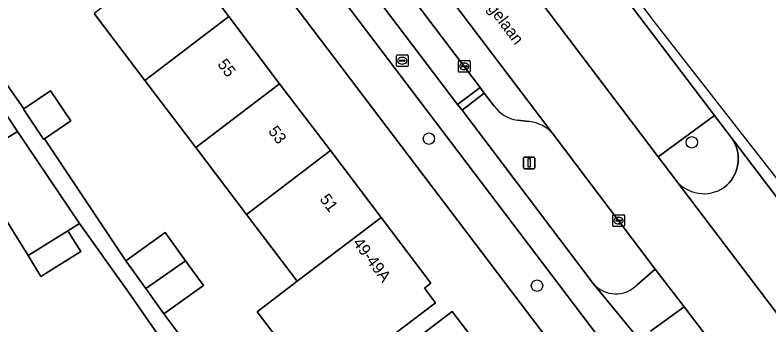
# Model space of a CAD drawing. Extents: x 159664 to 160323, y 385312 to 386115.
# Drawn here: x 160147.9 to 160212.4, y 385837.5 to 385864 of the extents above; entities that cross this region are included whole.
import ezdxf

# ---------------------------------------------------------------- set-up
doc = ezdxf.new("R2010")
doc.units = 0
for name, color, linetype in [('IMGEO_Berm_groen', 7, 'Continuous'), ('IMGEO_Boom', 7, 'Continuous'), ('IMGEO_Erf', 7, 'Continuous'), ('IMGEO_Fietspad_gesloten', 7, 'Continuous'), ('IMGEO_Kolk', 7, 'Continuous'), ('IMGEO_Lichtmast', 7, 'Continuous'), ('IMGEO_Openbare_ruimte_label', 7, 'Continuous'), ('IMGEO_Pand', 7, 'Continuous'), ('IMGEO_Pand_nummerreeks', 7, 'Continuous'), ('IMGEO_Parkeervlak_open', 7, 'Continuous'), ('IMGEO_Rijbaan_lokaal_gesloten', 7, 'Continuous'), ('IMGEO_Rioolput', 7, 'Continuous'), ('IMGEO_Verkeerseiland_groen', 7, 'Continuous'), ('IMGEO_Voetpad_open', 7, 'Continuous')]:
    doc.layers.add(name, color=color, linetype=linetype)

msp = doc.modelspace()

# ---------------------------------------------------------------- linework, layer by layer
at = {"layer": 'IMGEO_Berm_groen'}
for points in [[(160174.614, 385899.039), (160169.921, 385895.45), (160202.923, 385851.883), (160207.751, 385855.425)], [(160179.262, 385868.942), (160177.327, 385867.463), (160185.75, 385856.345), (160187.67, 385857.825)]]:
    msp.add_lwpolyline(points, close=True, dxfattribs=at)
for points in [[(160188.882, 385856.222), (160188.036, 385857.34), (160186.137, 385855.863), (160197.359, 385841.045)], [(160191.886, 385854.896), (160190.867, 385855.022)], [(160201.114, 385840.937), (160202.671, 385842.281), (160193.92, 385853.82)], [(160205.159, 385839.046), (160202.259, 385836.969)], [(160202.434, 385834.337), (160206.906, 385828.506), (160210.857, 385831.546), (160205.159, 385839.046)]]:
    msp.add_lwpolyline(points, dxfattribs=at)
for centre, radius, start, end in [((160191.266, 385857.924), 2.93, 215.52611, 262.16511), ((160191.589, 385851.873), 3.037, 39.86068, 84.38102), ((160199.286, 385842.7), 2.54, 220.65482, 316.05025)]:
    msp.add_arc(centre, radius, start, end, dxfattribs=at)
at = {"layer": 'IMGEO_Boom'}
for centre in [(160183.297, 385853.432), (160205.8, 385853.119), (160192.551, 385840.863)]:
    msp.add_circle(centre, 0.489, dxfattribs=at)
at = {"layer": 'IMGEO_Erf'}
for points in [[(160260.143, 385748.478), (160154.34, 385887.843), (160153.697, 385888.214), (160152.472, 385888.921), (160150.373, 385888.694), (160144.032, 385884.624)], [(160161.823, 385869.601), (160166.166, 385863.87), (160170.511, 385858.139), (160174.854, 385852.409), (160179.197, 385846.679), (160183.451, 385841.067), (160182.909, 385840.656), (160183.863, 385839.397), (160178.787, 385835.549), (160177.283, 385834.409), (160176.327, 385835.667), (160176.279, 385835.631), (160172.852, 385833.035), (160168.601, 385838.632), (160172.025, 385841.233), (160167.677, 385846.959), (160163.328, 385852.685), (160158.979, 385858.412), (160154.631, 385864.138)], [(160145.158, 385860.878), (160148.597, 385855.979), (160150.896, 385857.53), (160152.631, 385854.958), (160150.371, 385853.432), (160157.337, 385842.993), (160160.719, 385845.421), (160162.464, 385842.99), (160163.981, 385840.878), (160160.598, 385838.449), (160163.342, 385834.802)], [(160144.304, 385851.707), (160148.063, 385854.043), (160146.068, 385857.054)], [(160179.548, 385808.743), (160177.486, 385807.335), (160175.299, 385810.539), (160177.239, 385811.863), (160173.738, 385816.876), (160169.705, 385814.157), (160166.521, 385818.879), (160170.555, 385821.598), (160157.572, 385840.316), (160153.37, 385846.177), (160152.384, 385845.564), (160153.492, 385843.783), (160150.075, 385841.657), (160148.967, 385843.438), (160143.966, 385851.479)]]:
    msp.add_lwpolyline(points, dxfattribs=at)
msp.add_lwpolyline([(160208.692, 385793.17), (160204.334, 385798.89), (160199.977, 385804.609), (160195.619, 385810.328), (160191.261, 385816.048), (160186.904, 385821.767), (160182.547, 385827.485), (160178.162, 385833.241), (160181.313, 385835.637), (160185.293, 385838.663), (160189.676, 385832.899), (160194.027, 385827.176), (160198.379, 385821.452), (160202.731, 385815.729), (160207.083, 385810.005), (160211.435, 385804.281), (160215.786, 385798.558), (160220.204, 385792.748), (160215.947, 385789.652), (160213.003, 385787.512)], close=True, dxfattribs=at)
at = {"layer": 'IMGEO_Fietspad_gesloten'}
for points in [[(160201.804, 385835.617), (160197.359, 385841.045), (160186.137, 385855.863), (160185.75, 385856.345), (160177.327, 385867.463), (160175.871, 385869.409), (160168.561, 385878.986), (160168.182, 385879.472), (160161.323, 385888.557), (160159.511, 385890.971), (160157.24, 385893.946), (160149.098, 385905.226), (160147.316, 385907.817), (160144.932, 385911.316), (160142.935, 385909.961), (160147.03, 385903.951), (160154.766, 385893.221), (160263.854, 385749.476), (160272.35, 385738.304), (160298.51, 385703.942), (160300.884, 385700.823)], [(160202.671, 385842.281), (160201.114, 385840.937)], [(160202.259, 385836.969), (160205.159, 385839.046), (160202.671, 385842.281)], [(160197.359, 385841.045), (160201.804, 385835.617)]]:
    msp.add_lwpolyline(points, dxfattribs=at)
msp.add_arc((160199.286, 385842.7), 2.54, 220.65482, 316.05025, dxfattribs=at)
at = {"layer": 'IMGEO_Kolk'}
for p, q in [((160185.816, 385859.192), (160185.816, 385860.044)), ((160185.891, 385860.118), (160186.743, 385860.118)), ((160186.075, 385859.612), (160186.075, 385859.624)), ((160186.513, 385859.575), (160186.115, 385859.575)), ((160186.118, 385859.661), (160186.516, 385859.661)), ((160186.304, 385859.898), (160186.329, 385859.898)), ((160186.559, 385859.624), (160186.559, 385859.612)), ((160186.817, 385860.044), (160186.817, 385859.192)), ((160186.743, 385859.118), (160185.891, 385859.118)), ((160186.327, 385859.338), (160186.302, 385859.338)), ((160199.033, 385846.005), (160199.033, 385846.857)), ((160199.108, 385846.931), (160199.96, 385846.931)), ((160199.521, 385846.711), (160199.546, 385846.711)), ((160200.034, 385846.857), (160200.034, 385846.005)), ((160199.292, 385846.425), (160199.292, 385846.437)), ((160199.73, 385846.388), (160199.332, 385846.388)), ((160199.335, 385846.474), (160199.733, 385846.474)), ((160199.544, 385846.151), (160199.519, 385846.151)), ((160199.776, 385846.437), (160199.776, 385846.425)), ((160199.96, 385845.931), (160199.108, 385845.931))]:
    msp.add_line(p, q, dxfattribs=at)
for points in [[(160185.816, 385859.192), (160185.816, 385860.044)], [(160185.891, 385860.118), (160186.743, 385860.118)], [(160186.817, 385860.044), (160186.817, 385859.192)], [(160186.743, 385859.118), (160185.891, 385859.118)], [(160199.033, 385846.005), (160199.033, 385846.857)], [(160199.108, 385846.931), (160199.96, 385846.931)], [(160200.034, 385846.857), (160200.034, 385846.005)], [(160199.96, 385845.931), (160199.108, 385845.931)]]:
    msp.add_lwpolyline(points, dxfattribs=at)
for centre, radius, start, end in [((160185.893, 385860.042), 0.0765, 91.55205, 178.44795), ((160185.893, 385860.042), 0.0765, 91.55205, 178.44795), ((160186.115, 385859.621), 0.0403, 85.87752, 175.75265), ((160186.112, 385859.611), 0.0366, 178.93798, 274.71019), ((160186.516, 385859.618), 0.043, 264.86636, 352.45326), ((160186.52, 385859.623), 0.0386, 1.73085, 96.63898), ((160186.741, 385860.042), 0.0765, 1.55205, 88.44795), ((160186.741, 385860.042), 0.0765, 1.55205, 88.44795), ((160185.893, 385859.194), 0.0765, 181.55205, 268.44795), ((160185.893, 385859.194), 0.0765, 181.55205, 268.44795), ((160186.741, 385859.194), 0.0765, 271.55205, 358.44795), ((160186.741, 385859.194), 0.0765, 271.55205, 358.44795), ((160199.11, 385846.855), 0.0765, 91.55205, 178.44795), ((160199.11, 385846.855), 0.0765, 91.55205, 178.44795), ((160199.958, 385846.855), 0.0765, 1.55205, 88.44795), ((160199.958, 385846.855), 0.0765, 1.55205, 88.44795), ((160199.11, 385846.007), 0.0765, 181.55205, 268.44795), ((160199.11, 385846.007), 0.0765, 181.55205, 268.44795), ((160199.332, 385846.434), 0.0403, 85.87752, 175.75265), ((160199.329, 385846.424), 0.0366, 178.93798, 274.71019), ((160199.733, 385846.431), 0.043, 264.86636, 352.45326), ((160199.737, 385846.436), 0.0386, 1.73085, 96.63898), ((160199.958, 385846.007), 0.0765, 271.55205, 358.44795), ((160199.958, 385846.007), 0.0765, 271.55205, 358.44795)]:
    msp.add_arc(centre, radius, start, end, dxfattribs=at)
for centre, major_axis, ratio, start_param, end_param in [((160186.303, 385859.618), (-0.387, 0.002), 0.722429, 4.712389, 7.853982), ((160186.328, 385859.618), (-0.39, 0.002), 0.717154, 1.570796, 4.712389), ((160199.52, 385846.431), (-0.387, 0.002), 0.722429, 4.712389, 7.853982), ((160199.545, 385846.431), (-0.39, 0.002), 0.717154, 1.570796, 4.712389)]:
    msp.add_ellipse(centre, major_axis=major_axis, ratio=ratio, start_param=start_param, end_param=end_param, dxfattribs=at)
at = {"layer": 'IMGEO_Lichtmast'}
for p, q in [((160191.483, 385851.859), (160192.273, 385851.859)), ((160192.273, 385851.859), (160191.483, 385851.859)), ((160191.383, 385850.959), (160191.383, 385851.759)), ((160191.383, 385851.759), (160191.383, 385850.959)), ((160192.373, 385851.759), (160192.373, 385850.959)), ((160192.373, 385850.959), (160192.373, 385851.759)), ((160192.273, 385850.859), (160191.483, 385850.859)), ((160191.483, 385850.859), (160192.273, 385850.859))]:
    msp.add_line(p, q, dxfattribs=at)
msp.add_lwpolyline([(160191.803, 385851.734), (160191.953, 385851.734), (160191.953, 385850.984), (160191.803, 385850.984), (160191.803, 385851.734)], dxfattribs=at)
for centre, start, end in [((160191.483, 385851.759), 90, 180), ((160191.483, 385851.759), 90, 180), ((160192.273, 385851.759), 0, 90), ((160192.273, 385851.759), 360, 90), ((160191.483, 385850.959), 180, 270), ((160191.483, 385850.959), 180, 270), ((160192.273, 385850.959), 270, 0), ((160192.273, 385850.959), 270, 0)]:
    msp.add_arc(centre, 0.1, start, end, dxfattribs=at)
at = {"layer": 'IMGEO_Pand'}
for points in [[(160166.166, 385863.87), (160161.823, 385869.601), (160154.631, 385864.138), (160158.979, 385858.412)], [(160158.979, 385858.412), (160163.328, 385852.685), (160170.511, 385858.139), (160166.166, 385863.87)], [(160174.854, 385852.409), (160170.511, 385858.139), (160163.328, 385852.685), (160167.677, 385846.959)], [(160148.597, 385855.979), (160148.568, 385855.96), (160150.304, 385853.387), (160150.371, 385853.432), (160152.631, 385854.958), (160150.896, 385857.53)], [(160148.063, 385854.043), (160144.304, 385851.707), (160143.966, 385851.479), (160148.967, 385843.438), (160152.384, 385845.564), (160153.37, 385846.177)], [(160167.677, 385846.959), (160172.025, 385841.233), (160179.197, 385846.679), (160174.854, 385852.409)], [(160183.863, 385839.397), (160182.909, 385840.656), (160183.451, 385841.067), (160179.197, 385846.679), (160172.025, 385841.233), (160168.601, 385838.632), (160172.852, 385833.035), (160176.279, 385835.631), (160176.327, 385835.667), (160177.283, 385834.409), (160178.787, 385835.549)], [(160148.967, 385843.438), (160150.075, 385841.657), (160153.492, 385843.783), (160152.384, 385845.564)], [(160157.337, 385842.993), (160159.042, 385840.617), (160162.464, 385842.99), (160160.719, 385845.421)], [(160163.981, 385840.878), (160162.464, 385842.99), (160159.042, 385840.617), (160160.598, 385838.449)], [(160189.676, 385832.899), (160185.293, 385838.663), (160181.313, 385835.637), (160178.162, 385833.241), (160182.547, 385827.485)]]:
    msp.add_lwpolyline(points, close=True, dxfattribs=at)
at = {"layer": 'IMGEO_Parkeervlak_open'}
for points in [[(160193.92, 385853.82), (160166.706, 385889.723)], [(160167.67, 385884.268), (160170.13, 385881.015), (160170.512, 385880.51), (160177.807, 385870.864), (160179.262, 385868.942), (160187.67, 385857.825), (160188.036, 385857.34), (160188.882, 385856.222)], [(160190.867, 385855.022), (160191.886, 385854.896)]]:
    msp.add_lwpolyline(points, dxfattribs=at)
for centre, radius, start, end in [((160191.266, 385857.924), 2.93, 215.52611, 262.16511), ((160191.589, 385851.873), 3.037, 39.86068, 84.38102)]:
    msp.add_arc(centre, radius, start, end, dxfattribs=at)
at = {"layer": 'IMGEO_Rijbaan_lokaal_gesloten'}
for points in [[(160278.119, 385766.625), (160272.577, 385773.993), (160202.503, 385863.561), (160175.453, 385899.617), (160174.614, 385899.039), (160207.751, 385855.425), (160209.198, 385853.52), (160209.222, 385853.486), (160218.049, 385841.864), (160218.207, 385841.662), (160220.49, 385838.634), (160222.308, 385836.246), (160276.21, 385765.273)], [(160169.921, 385895.45), (160165.321, 385891.586), (160166.706, 385889.723), (160193.92, 385853.82), (160202.671, 385842.281), (160205.159, 385839.046), (160210.857, 385831.546), (160212.699, 385829.104), (160214.504, 385826.716), (160264.977, 385760.314), (160266.788, 385757.939), (160271.472, 385761.661), (160217.534, 385832.65), (160215.717, 385835.043), (160213.549, 385837.897), (160213.521, 385837.931), (160204.43, 385849.882), (160204.376, 385849.964), (160202.923, 385851.883)]]:
    msp.add_lwpolyline(points, close=True, dxfattribs=at)
for points in [[(160209.222, 385853.486), (160209.371, 385853.253), (160209.498, 385853.007), (160209.602, 385852.752), (160209.684, 385852.488), (160209.741, 385852.218), (160209.774, 385851.943), (160209.783, 385851.667), (160209.766, 385851.392), (160209.726, 385851.118), (160209.66, 385850.85), (160209.572, 385850.588), (160209.46, 385850.336), (160209.326, 385850.094), (160209.171, 385849.866), (160208.996, 385849.652), (160208.803, 385849.454), (160208.593, 385849.275)], [(160214.014, 385842.176), (160214.119, 385842.262), (160214.328, 385842.409), (160214.55, 385842.538), (160214.782, 385842.646), (160215.023, 385842.733), (160215.271, 385842.798), (160215.524, 385842.841), (160215.779, 385842.861), (160216.036, 385842.858), (160216.291, 385842.832), (160216.542, 385842.784), (160216.789, 385842.713), (160217.028, 385842.62), (160217.257, 385842.507), (160217.476, 385842.373), (160217.682, 385842.221), (160217.873, 385842.05), (160218.049, 385841.864), (160209.222, 385853.486)], [(160204.376, 385849.964), (160204.43, 385849.882), (160213.521, 385837.931), (160213.549, 385837.897)]]:
    msp.add_lwpolyline(points, dxfattribs=at)
msp.add_arc((160206.841, 385851.801), 3.074, 216.69053, 304.75076, dxfattribs=at)
at = {"layer": 'IMGEO_Rioolput'}
for p, q in [((160180.512, 385859.674), (160180.512, 385860.526)), ((160180.587, 385860.6), (160181.439, 385860.6)), ((160181, 385860.38), (160181.025, 385860.38)), ((160181.513, 385860.526), (160181.513, 385859.674)), ((160181.439, 385859.6), (160180.587, 385859.6)), ((160180.771, 385860.094), (160180.771, 385860.106)), ((160181.209, 385860.057), (160180.811, 385860.057)), ((160180.814, 385860.143), (160181.212, 385860.143)), ((160181.023, 385859.82), (160180.998, 385859.82)), ((160181.255, 385860.106), (160181.255, 385860.094))]:
    msp.add_line(p, q, dxfattribs=at)
for points in [[(160180.512, 385859.674), (160180.512, 385860.526)], [(160180.587, 385860.6), (160181.439, 385860.6)], [(160181.513, 385860.526), (160181.513, 385859.674)], [(160181.439, 385859.6), (160180.587, 385859.6)]]:
    msp.add_lwpolyline(points, dxfattribs=at)
for centre, radius, start, end in [((160180.589, 385860.524), 0.0765, 91.55205, 178.44795), ((160180.589, 385860.524), 0.0765, 91.55205, 178.44795), ((160181.437, 385860.524), 0.0765, 1.55205, 88.44795), ((160181.437, 385860.524), 0.0765, 1.55205, 88.44795), ((160180.589, 385859.676), 0.0765, 181.55205, 268.44795), ((160180.589, 385859.676), 0.0765, 181.55205, 268.44795), ((160180.811, 385860.103), 0.0403, 85.87752, 175.75265), ((160180.808, 385860.093), 0.0366, 178.93798, 274.71019), ((160181.212, 385860.1), 0.043, 264.86636, 352.45326), ((160181.216, 385860.105), 0.0386, 1.73085, 96.63898), ((160181.437, 385859.676), 0.0765, 271.55205, 358.44795), ((160181.437, 385859.676), 0.0765, 271.55205, 358.44795)]:
    msp.add_arc(centre, radius, start, end, dxfattribs=at)
for centre, major_axis, ratio, start_param, end_param in [((160180.999, 385860.1), (-0.387, 0.002), 0.722429, 4.712389, 7.853982), ((160181.024, 385860.1), (-0.39, 0.002), 0.717154, 1.570796, 4.712389)]:
    msp.add_ellipse(centre, major_axis=major_axis, ratio=ratio, start_param=start_param, end_param=end_param, dxfattribs=at)
at = {"layer": 'IMGEO_Verkeerseiland_groen'}
for points in [[(160209.66, 385850.85), (160209.726, 385851.118), (160209.766, 385851.392), (160209.783, 385851.667), (160209.774, 385851.943), (160209.741, 385852.218), (160209.684, 385852.488), (160209.602, 385852.752), (160209.498, 385853.007), (160209.371, 385853.253), (160209.222, 385853.486), (160209.198, 385853.52), (160207.751, 385855.425), (160202.923, 385851.883), (160204.376, 385849.964)], [(160208.593, 385849.275), (160208.803, 385849.454), (160208.996, 385849.652), (160209.171, 385849.866), (160209.326, 385850.094), (160209.46, 385850.336), (160209.572, 385850.588), (160209.66, 385850.85)]]:
    msp.add_lwpolyline(points, dxfattribs=at)
msp.add_arc((160206.841, 385851.801), 3.074, 216.69053, 304.75076, dxfattribs=at)
at = {"layer": 'IMGEO_Voetpad_open'}
for points in [[(160151.188, 385893.955), (160154.34, 385887.843), (160260.143, 385748.478), (160263.491, 385744.011)], [(160263.854, 385749.476), (160154.766, 385893.221)], [(160200.775, 385780.416), (160195.294, 385788.767), (160193.731, 385790.839), (160191.803, 385793.392), (160187.034, 385800.478), (160185.516, 385802.657), (160183.731, 385805.222), (160179, 385812.123), (160177.151, 385814.574), (160175.556, 385816.688), (160170.001, 385825.278), (160168.297, 385827.705), (160166.643, 385830.062), (160163.342, 385834.802), (160160.598, 385838.449), (160159.042, 385840.617), (160157.337, 385842.993), (160150.371, 385853.432), (160150.304, 385853.387), (160148.568, 385855.96), (160148.597, 385855.979), (160145.158, 385860.878)], [(160146.068, 385857.054), (160148.063, 385854.043), (160153.37, 385846.177), (160157.572, 385840.316), (160170.555, 385821.598), (160173.738, 385816.876), (160177.239, 385811.863), (160177.361, 385811.946), (160179.548, 385808.743), (160189.127, 385794.678), (160190.777, 385792.391), (160193.661, 385788.39), (160193.275, 385788.112), (160193.825, 385787.32)]]:
    msp.add_lwpolyline(points, dxfattribs=at)
msp.add_lwpolyline([(160186.137, 385855.863), (160188.036, 385857.34), (160187.67, 385857.825), (160185.75, 385856.345)], close=True, dxfattribs=at)

# ---------------------------------------------------------------- texts
at = {"layer": 'IMGEO_Openbare_ruimte_label'}
msp.add_text('Dr Berlagelaan', height=1, rotation=307.15637, dxfattribs=at).set_placement((160185.314, 385868.492))
at = {"layer": 'IMGEO_Pand_nummerreeks'}
for s, rotation, p in [('55', 307.16212, (160165.142, 385859.792)), ('53', 307.16212, (160169.484, 385854.064)), ('51', 307.16212, (160173.894, 385848.246)), ('49-49A', 307.16183, (160176.73, 385844.505))]:
    msp.add_text(s, height=1, rotation=rotation, dxfattribs=at).set_placement(p)

doc.saveas('drawing.dxf')
